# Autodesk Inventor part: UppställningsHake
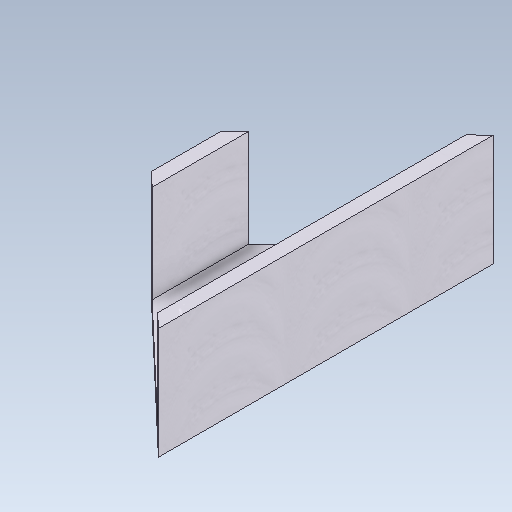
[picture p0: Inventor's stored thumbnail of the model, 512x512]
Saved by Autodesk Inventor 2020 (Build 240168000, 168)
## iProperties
Created: 2019-06
Part Number: UppställningsHake
Material: Aluminum 6061, Welded
Document SubType Name: Modeling
Designer: cl
Density: 2.7 g/cm^3
Appearance: Weld - Aluminum
Author: cl
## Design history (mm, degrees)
sketch "Sketch1"
  geometry: L1 (0, 0)-(0, -120); L2 (0, -120)-(50, -72.5); L3 (50, -72.5)-(50, -47.5); L4 (50, -47.5)-(0, 0); L5 (74.044, -60)-(-45.139, -60)
  constraints: 10 end point, 1 horizontal, 1 parallel, 1 vertical
  dimensions: "d0" = 120 distance of L1.start L1.end; "d1" = 25 distance of L2.end L3.end; "d3" = 60 distance from line of L1.start L5; "d4" = 12.5 distance from line of L3.end L5; "d5" = 50 distance between parallel lines of L3 L1
extrude "Extrusion1" new body sketch "Sketch1" distance "d6" = 5; taper "d7" = 0 deg
sketch "Sketch2"
  geometry: L1 (0, 0)-(0, 120) reference; L2 (0, 0)-(0, 120); L3 (0, 120)-(-5, 115.25); L4 (-5, 115.25)-(-5, 4.75); L5 (-5, 4.75)-(0, 0); L6 (-50, 47.5)-(0, 0) reference; L7 (0, 120)-(-50, 72.5) reference; L8 (-50, 72.5)-(-50, 47.5) reference; L9 (-50, 47.5)-(-45, 42.75); L10 (-45, 42.75)-(-45, 77.25); L11 (-45, 77.25)-(-50, 72.5); L12 (-50, 72.5)-(-50, 47.5); 1 further point
  constraints: 16 end point, 4 collinear, 2 point on line, 2 vertical, 1 parallel
  dimensions: "d8" = 5 distance between parallel lines of L1 L4; "d10" = 5 distance between parallel lines of L8 L10
extrude "Extrusion2" join sketch "Sketch2" distance "d11" = 35; taper "d12" = 0 deg
body "Solid1"
